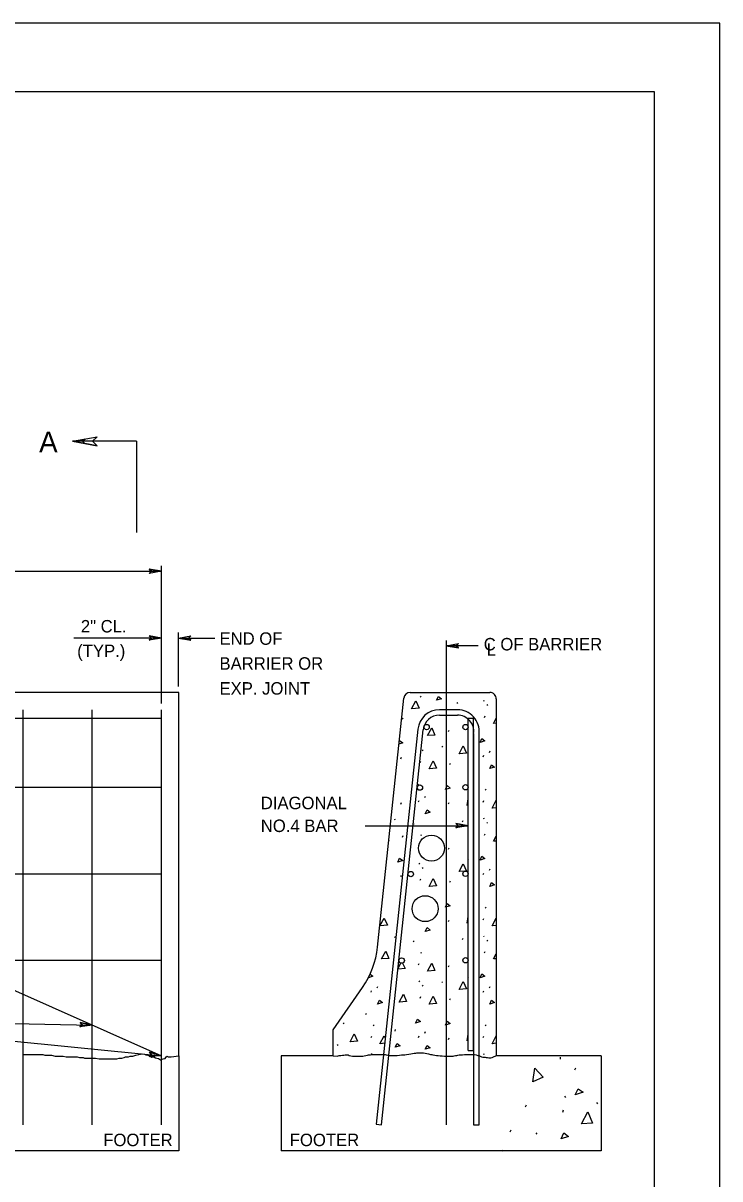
# Model space of a CAD drawing. Extents: x -113.6 to -105.1, y -201.8 to -190.8.
# Drawn here: x -108.47 to -105.11, y -196.35 to -190.78 of the extents above; entities that cross this region are included whole.
import ezdxf

# ---------------------------------------------------------------- set-up
doc = ezdxf.new("R2010")
doc.units = 0
for name, color, linetype in [('BORD-LINE', 7, 'Continuous'), ('CLIN', 7, 'Continuous'), ('DETL-PATT', 7, 'Continuous'), ('Level 10', 7, 'Continuous'), ('Level 12', 7, 'Continuous'), ('LGHT-UTIL_P', 7, 'Continuous'), ('SUBS-FOOT_P', 7, 'Continuous'), ('SUPR-PARA_P', 7, 'Continuous'), ('SUPR-RFRC', 7, 'Continuous'), ('USER-CLIP', 7, 'Continuous')]:
    doc.layers.add(name, color=color, linetype=linetype)

msp = doc.modelspace()

# ---------------------------------------------------------------- linework, layer by layer
at = {"layer": 'BORD-LINE'}
msp.add_lwpolyline([(-112.8058, -191.1077), (-105.4316, -191.1077), (-105.4316, -201.4608), (-112.8058, -201.4608)], close=True, dxfattribs=at)
at = {"layer": 'CLIN'}
msp.add_line((-106.4326, -193.7529), (-106.4326, -196.0862), dxfattribs=at)
at = {"layer": 'DETL-PATT'}
for p, q in [((-106.5997, -194.0811), (-106.5794, -194.0429)), ((-106.5794, -194.0429), (-106.5637, -194.078)), ((-106.5575, -194.0209), (-106.5545, -194.0253)), ((-106.3813, -194.0518), (-106.3783, -194.0564)), ((-106.2538, -194.0402), (-106.2508, -194.0448)), ((-106.2375, -194.0614), (-106.2345, -194.0661)), ((-106.6436, -194.1323), (-106.6407, -194.1255)), ((-106.5637, -194.078), (-106.5989, -194.0811)), ((-106.2476, -194.1227), (-106.2447, -194.1161)), ((-106.2047, -194.1524), (-106.1914, -194.1273)), ((-106.4219, -194.1909), (-106.4189, -194.1841)), ((-106.1914, -194.1513), (-106.2039, -194.1524)), ((-106.3286, -194.2386), (-106.3269, -194.2412)), ((-106.5484, -194.2791), (-106.5454, -194.2838)), ((-106.4537, -194.2618), (-106.4507, -194.2664)), ((-106.3708, -194.2988), (-106.3505, -194.2607)), ((-106.3348, -194.2958), (-106.37, -194.2988)), ((-106.3505, -194.2607), (-106.3348, -194.2958)), ((-106.2248, -194.2914), (-106.2218, -194.2846)), ((-106.6512, -194.3219), (-106.6482, -194.3153)), ((-106.5585, -194.3405), (-106.5556, -194.3338)), ((-106.4147, -194.3501), (-106.4117, -194.3433)), ((-106.2551, -194.3123), (-106.2522, -194.3056)), ((-106.5721, -194.4583), (-106.5722, -194.4584)), ((-106.5706, -194.4433), (-106.5632, -194.4488)), ((-106.5357, -194.5091), (-106.5327, -194.5024)), ((-106.3313, -194.5475), (-106.3269, -194.5154)), ((-106.2447, -194.4695), (-106.2417, -194.4741)), ((-106.6509, -194.5404), (-106.6479, -194.5337)), ((-106.566, -194.5301), (-106.5631, -194.5234)), ((-106.4223, -194.5396), (-106.4192, -194.5331)), ((-106.3269, -194.5454), (-106.3306, -194.5471)), ((-106.2548, -194.5308), (-106.2519, -194.5241)), ((-106.1914, -194.5588), (-106.2112, -194.5605)), ((-106.6826, -194.6114), (-106.6796, -194.616)), ((-106.3542, -194.6263), (-106.3513, -194.6195)), ((-106.2538, -194.6075), (-106.2508, -194.6121)), ((-106.2375, -194.6287), (-106.2345, -194.6333)), ((-106.5907, -194.6342), (-106.5887, -194.6372)), ((-106.5556, -194.6872), (-106.5526, -194.6918)), ((-106.2476, -194.69), (-106.2447, -194.6833)), ((-106.6436, -194.6996), (-106.6407, -194.6928)), ((-106.2047, -194.7197), (-106.1914, -194.6946)), ((-106.1914, -194.7186), (-106.2039, -194.7197)), ((-106.4219, -194.7582), (-106.4189, -194.7514)), ((-106.5647, -194.8253), (-106.5616, -194.8299)), ((-106.5484, -194.8464), (-106.5454, -194.8511)), ((-106.3708, -194.8661), (-106.3505, -194.828)), ((-106.3505, -194.828), (-106.3348, -194.8631)), ((-106.3286, -194.8059), (-106.3269, -194.8085)), ((-106.2248, -194.8587), (-106.2218, -194.8519)), ((-106.6512, -194.8892), (-106.6482, -194.8826)), ((-106.5585, -194.9078), (-106.5556, -194.9011)), ((-106.3423, -194.8637), (-106.37, -194.8661)), ((-106.3348, -194.8631), (-106.3397, -194.8635)), ((-106.2551, -194.8796), (-106.2522, -194.8729)), ((-106.4147, -194.9174), (-106.4117, -194.9106)), ((-106.2447, -195.0368), (-106.2417, -195.0414)), ((-106.4223, -195.1069), (-106.4192, -195.1004)), ((-106.3313, -195.1147), (-106.3269, -195.0827)), ((-106.3269, -195.1127), (-106.3306, -195.1144)), ((-106.2548, -195.0981), (-106.2519, -195.0914)), ((-106.1914, -195.1261), (-106.2112, -195.1278)), ((-106.6826, -195.1787), (-106.6796, -195.1832)), ((-106.3542, -195.1936), (-106.3513, -195.1868)), ((-106.2538, -195.1748), (-106.2508, -195.1794)), ((-106.5917, -195.2), (-106.5887, -195.2045)), ((-106.2375, -195.196), (-106.2345, -195.2006)), ((-106.5556, -195.2545), (-106.5526, -195.2591)), ((-106.2476, -195.2573), (-106.2447, -195.2506)), ((-106.2047, -195.287), (-106.1914, -195.2619)), ((-106.1914, -195.2859), (-106.2039, -195.287)), ((-106.6643, -195.3318), (-106.6512, -195.307)), ((-106.5657, -195.3159), (-106.5628, -195.3091)), ((-106.4219, -195.3255), (-106.4189, -195.3187)), ((-106.5647, -195.3926), (-106.5616, -195.3971)), ((-106.4537, -195.3964), (-106.4507, -195.401)), ((-106.3708, -195.4334), (-106.3505, -195.3953)), ((-106.3505, -195.3953), (-106.3348, -195.4304)), ((-106.3286, -195.3732), (-106.3269, -195.3758)), ((-106.7949, -195.4469), (-106.792, -195.4402)), ((-106.7646, -195.426), (-106.7616, -195.4192)), ((-106.5484, -195.4137), (-106.5454, -195.4184)), ((-106.3348, -195.4304), (-106.37, -195.4334)), ((-106.2551, -195.4469), (-106.2522, -195.4402)), ((-106.2248, -195.426), (-106.2218, -195.4192)), ((-106.5585, -195.4751), (-106.5556, -195.4684)), ((-106.4147, -195.4846), (-106.4117, -195.4779)), ((-106.8207, -195.5495), (-106.8176, -195.5541)), ((-106.9283, -195.5945), (-106.9254, -195.5991)), ((-106.7845, -195.6041), (-106.7815, -195.6087)), ((-106.6794, -195.6341), (-106.6764, -195.6274)), ((-106.2447, -195.6041), (-106.2417, -195.6087)), ((-106.7946, -195.6654), (-106.7917, -195.6587)), ((-106.566, -195.6646), (-106.5631, -195.658)), ((-106.5357, -195.6437), (-106.5327, -195.6369)), ((-106.4223, -195.6742), (-106.4192, -195.6677)), ((-106.3313, -195.682), (-106.3269, -195.65)), ((-106.3269, -195.68), (-106.3306, -195.6817)), ((-106.2548, -195.6654), (-106.2519, -195.6587)), ((-106.9575, -195.699), (-106.9546, -195.7035)), ((-106.7936, -195.7421), (-106.7906, -195.7467)), ((-106.7286, -195.6932), (-106.751, -195.6951)), ((-106.6781, -195.7126), (-106.669, -195.6938)), ((-106.6542, -195.7051), (-106.6781, -195.7126)), ((-106.669, -195.6938), (-106.6542, -195.7051)), ((-106.2538, -195.7421), (-106.2508, -195.7467)), ((-106.1914, -195.6934), (-106.2112, -195.6951)), ((-105.8847, -195.7593), (-105.8834, -195.7696)), ((-105.8126, -195.8212), (-105.8087, -195.8109)), ((-105.8628, -195.9487), (-105.859, -195.9551)), ((-106.0509, -196.0002), (-106.0457, -195.9899)), ((-105.8718, -196.0247), (-105.868, -196.0144)), ((-105.7095, -195.9783), (-105.7044, -195.9848)), ((-106.125, -196.1201), (-106.1198, -196.1098)), ((-106.0007, -196.1239), (-105.9955, -196.1316))]:
    msp.add_line(p, q, dxfattribs=at)
for points in [[(-106.4791, -194.0402), (-106.4701, -194.0216), (-106.4553, -194.0328), (-106.4791, -194.0402)], [(-106.5228, -194.211), (-106.5026, -194.1729), (-106.4868, -194.208), (-106.522, -194.211)], [(-106.6589, -194.2382), (-106.657, -194.2342), (-106.6419, -194.2454), (-106.6603, -194.2512)], [(-106.2699, -194.2433), (-106.261, -194.2246), (-106.246, -194.2357), (-106.2699, -194.2433)], [(-106.5156, -194.3702), (-106.4954, -194.332), (-106.4797, -194.3671), (-106.5148, -194.3702)], [(-106.2233, -194.3698), (-106.2143, -194.3511), (-106.1995, -194.3623), (-106.2233, -194.3698)], [(-106.4369, -194.4707), (-106.4281, -194.4519), (-106.413, -194.4632), (-106.4369, -194.4707)], [(-106.5341, -194.5876), (-106.5252, -194.5688), (-106.5104, -194.5801), (-106.5341, -194.5876)], [(-106.2119, -194.5605), (-106.1917, -194.5224), (-106.1914, -194.5231)], [(-106.7092, -194.7152), (-106.7086, -194.7167), (-106.7094, -194.7168)], [(-106.2699, -194.8106), (-106.261, -194.7919), (-106.246, -194.803), (-106.2699, -194.8106)], [(-106.6659, -194.8202), (-106.657, -194.8015), (-106.6419, -194.8127), (-106.6659, -194.8202)], [(-106.5156, -194.9375), (-106.4954, -194.8993), (-106.4797, -194.9344), (-106.5148, -194.9375)], [(-106.2233, -194.9371), (-106.2143, -194.9183), (-106.1995, -194.9296), (-106.2233, -194.9371)], [(-106.4369, -195.038), (-106.4281, -195.0192), (-106.413, -195.0305), (-106.4369, -195.038)], [(-106.7517, -195.1278), (-106.7315, -195.0897), (-106.7158, -195.1248), (-106.751, -195.1278)], [(-106.2119, -195.1278), (-106.1917, -195.0897), (-106.1914, -195.0904)], [(-106.5341, -195.1549), (-106.5252, -195.1361), (-106.5104, -195.1474), (-106.5341, -195.1549)], [(-106.7445, -195.287), (-106.7243, -195.2489), (-106.7086, -195.284), (-106.7437, -195.287)], [(-106.6425, -195.3067), (-106.6306, -195.333), (-106.6647, -195.3359)], [(-106.5228, -195.3456), (-106.5026, -195.3075), (-106.4868, -195.3426), (-106.522, -195.3456)], [(-106.7995, -195.3601), (-106.7858, -195.3703), (-106.8078, -195.3773)], [(-106.2699, -195.3779), (-106.261, -195.3592), (-106.246, -195.3703), (-106.2699, -195.3779)], [(-106.6593, -195.4952), (-106.6391, -195.4571), (-106.6234, -195.4921), (-106.6586, -195.4952)], [(-106.5156, -195.5047), (-106.4954, -195.4666), (-106.4797, -195.5017), (-106.5148, -195.5047)], [(-106.7631, -195.5044), (-106.7541, -195.4856), (-106.7393, -195.4969), (-106.7631, -195.5044)], [(-106.2233, -195.5044), (-106.2143, -195.4856), (-106.1995, -195.4969), (-106.2233, -195.5044)], [(-106.5808, -195.5957), (-106.5718, -195.5769), (-106.5568, -195.5881), (-106.5808, -195.5957)], [(-106.4369, -195.6053), (-106.4281, -195.5865), (-106.413, -195.5978), (-106.4369, -195.6053)], [(-106.8955, -195.6855), (-106.8754, -195.6475), (-106.8595, -195.6825), (-106.8947, -195.6855)], [(-106.7517, -195.6951), (-106.7315, -195.657), (-106.7261, -195.6691)], [(-106.2119, -195.6951), (-106.1917, -195.657), (-106.1914, -195.6577)], [(-106.5341, -195.7221), (-106.5252, -195.7034), (-106.5104, -195.7146), (-106.5341, -195.7221)], [(-106.0148, -195.8791), (-106.0058, -195.8134), (-105.9659, -195.8559), (-106.0148, -195.8791)], [(-105.8113, -195.941), (-105.7971, -195.9126), (-105.7739, -195.9294), (-105.8113, -195.941)], [(-105.7817, -196.0814), (-105.7507, -196.0234), (-105.7275, -196.0775), (-105.7817, -196.0814)], [(-105.8796, -196.1535), (-105.8667, -196.1252), (-105.8435, -196.1419), (-105.8796, -196.1535)], [(-106.1648, -196.2112), (-106.163, -196.2076), (-106.1583, -196.2112)]]:
    msp.add_lwpolyline(points, dxfattribs=at)
at = {"layer": 'Level 10'}
for p, q in [((-108.2326, -192.7927), (-108.1133, -192.7717)), ((-108.2326, -192.7927), (-108.173, -192.7822)), ((-108.2326, -192.7927), (-108.173, -192.8032)), ((-108.2326, -192.7927), (-108.1133, -192.8137)), ((-107.9246, -192.7927), (-108.2326, -192.7927)), ((-108.1843, -192.7927), (-108.173, -192.7822)), ((-108.173, -192.8032), (-108.1843, -192.7927)), ((-108.136, -192.7927), (-108.1133, -192.7717)), ((-108.1133, -192.8137), (-108.136, -192.7927)), ((-107.9246, -192.7927), (-107.9246, -193.2322)), ((-107.8038, -194.0567), (-107.8038, -193.3935)), ((-111.4705, -193.4185), (-107.8038, -193.4185)), ((-107.8038, -193.4185), (-107.8635, -193.408)), ((-107.8635, -193.408), (-107.8521, -193.4185)), ((-107.8038, -193.4185), (-107.8635, -193.429)), ((-107.8521, -193.4185), (-107.8635, -193.429)), ((-107.8038, -193.7407), (-107.8635, -193.7302)), ((-107.8635, -193.7302), (-107.8521, -193.7407)), ((-107.7223, -193.9734), (-107.7223, -193.7132)), ((-107.7223, -193.7407), (-107.6628, -193.7302)), ((-107.674, -193.7407), (-107.6628, -193.7302)), ((-107.8038, -193.7407), (-108.2267, -193.7407)), ((-107.8038, -193.7407), (-107.8635, -193.7512)), ((-107.8521, -193.7407), (-107.8635, -193.7512)), ((-107.7223, -193.7407), (-107.5471, -193.7407)), ((-107.7223, -193.7407), (-107.6628, -193.7512)), ((-107.6628, -193.7512), (-107.674, -193.7407)), ((-106.4326, -193.7779), (-106.3729, -193.7674)), ((-106.2789, -193.7779), (-106.4326, -193.7779)), ((-106.4326, -193.7779), (-106.3729, -193.7884)), ((-106.3842, -193.7779), (-106.3729, -193.7674)), ((-106.3729, -193.7884), (-106.3842, -193.7779)), ((-106.8232, -194.6453), (-106.3269, -194.6453)), ((-106.3269, -194.6453), (-106.3865, -194.6348)), ((-106.3865, -194.6348), (-106.3752, -194.6453)), ((-106.3269, -194.6453), (-106.3865, -194.6558)), ((-106.3752, -194.6453), (-106.3865, -194.6558)), ((-109.5686, -195.5773), (-108.1372, -195.6052)), ((-109.5686, -195.5773), (-107.8038, -195.7529)), ((-108.1854, -195.6042), (-108.1968, -195.6145)), ((-108.1372, -195.6052), (-108.1968, -195.6145)), ((-108.1372, -195.6052), (-108.1965, -195.5936)), ((-108.1965, -195.5936), (-108.1854, -195.6042)), ((-107.8038, -195.7529), (-107.862, -195.7366)), ((-107.862, -195.7366), (-107.8519, -195.7481)), ((-107.8519, -195.7481), (-107.8641, -195.7575)), ((-107.8038, -195.7529), (-107.8641, -195.7575))]:
    msp.add_line(p, q, dxfattribs=at)
for points in [[(-108.1133, -192.8137), (-108.2326, -192.7927), (-108.1133, -192.7717), (-108.136, -192.7927)], [(-108.173, -192.8032), (-108.2326, -192.7927), (-108.173, -192.7822), (-108.1843, -192.7927)], [(-107.8635, -193.408), (-107.8038, -193.4185), (-107.8635, -193.429), (-107.8521, -193.4185)], [(-107.8635, -193.7302), (-107.8038, -193.7407), (-107.8635, -193.7512), (-107.8521, -193.7407)], [(-107.6628, -193.7512), (-107.7223, -193.7407), (-107.6628, -193.7302), (-107.674, -193.7407)], [(-106.3729, -193.7884), (-106.4326, -193.7779), (-106.3729, -193.7674), (-106.3842, -193.7779)], [(-106.3865, -194.6348), (-106.3269, -194.6453), (-106.3865, -194.6558), (-106.3752, -194.6453)], [(-108.1965, -195.5936), (-108.1372, -195.6052), (-108.1968, -195.6145), (-108.1854, -195.6042)], [(-107.862, -195.7366), (-107.8038, -195.7529), (-107.8641, -195.7575), (-107.8519, -195.7481)]]:
    msp.add_lwpolyline(points, close=True, dxfattribs=at)
at = {"layer": 'LGHT-UTIL_P'}
for centre in [(-106.5037, -194.7529), (-106.5037, -194.7529), (-106.5345, -195.0446), (-106.5345, -195.0446)]:
    msp.add_circle(centre, 0.0625, dxfattribs=at)
at = {"layer": 'SUBS-FOOT_P'}
for p, q in [((-107.7205, -195.7529), (-107.7205, -196.2112)), ((-107.2279, -195.7529), (-107.2279, -196.2112)), ((-106.9779, -195.7529), (-107.2279, -195.7529)), ((-105.6862, -195.7529), (-106.1914, -195.7529)), ((-105.6862, -195.7529), (-105.6862, -196.2112)), ((-107.7205, -196.2112), (-112.302, -196.2112)), ((-105.6862, -196.2112), (-107.2279, -196.2112))]:
    msp.add_line(p, q, dxfattribs=at)
for points in [[(-108.4714, -195.7476), (-108.4608, -195.7476), (-108.4431, -195.7476), (-108.4255, -195.7476), (-108.4113, -195.7476), (-108.3972, -195.7476), (-108.3901, -195.7476), (-108.3831, -195.7476), (-108.376, -195.7476), (-108.3654, -195.7511), (-108.3513, -195.7511), (-108.3336, -195.7511), (-108.3159, -195.7546), (-108.3053, -195.7546), (-108.2983, -195.7546), (-108.2912, -195.7546), (-108.2841, -195.7546), (-108.2771, -195.7546), (-108.2629, -195.7582), (-108.2523, -195.7582), (-108.2453, -195.7582), (-108.2311, -195.7582), (-108.2241, -195.7582), (-108.2099, -195.7582), (-108.1993, -195.7617), (-108.1887, -195.7617), (-108.1817, -195.7617), (-108.1746, -195.7653), (-108.1675, -195.7653), (-108.1605, -195.7653), (-108.1499, -195.7653), (-108.1428, -195.7653), (-108.1287, -195.7653), (-108.1216, -195.7653), (-108.1039, -195.7688), (-108.0933, -195.7688), (-108.0827, -195.7688), (-108.0721, -195.7688), (-108.0615, -195.7688), (-108.0545, -195.7688), (-108.0474, -195.7688), (-108.0333, -195.7688), (-108.0262, -195.7688), (-108.0192, -195.7688), (-108.0086, -195.7653), (-108.0015, -195.7653), (-107.9944, -195.7653), (-107.9838, -195.7617), (-107.9768, -195.7582), (-107.9697, -195.7582), (-107.9626, -195.7582), (-107.9556, -195.7546), (-107.9414, -195.7546), (-107.9273, -195.7511), (-107.9132, -195.7476), (-107.8955, -195.744), (-107.8865, -195.7461), (-107.8787, -195.7486), (-107.8693, -195.75), (-107.8665, -195.7523), (-107.8595, -195.7536), (-107.8519, -195.7599), (-107.8406, -195.7578), (-107.8329, -195.7628), (-107.827, -195.7645), (-107.819, -195.7673), (-107.8083, -195.7724), (-107.7966, -195.7679), (-107.786, -195.7672), (-107.7789, -195.7546), (-107.7718, -195.7582), (-107.7648, -195.7582), (-107.7577, -195.7582), (-107.7205, -195.7529)], [(-106.9779, -195.7529), (-106.9584, -195.7548), (-106.948, -195.7527), (-106.9407, -195.7517), (-106.9324, -195.7506), (-106.9261, -195.7506), (-106.9199, -195.7496), (-106.9147, -195.7496), (-106.9053, -195.7496), (-106.9001, -195.7517), (-106.8918, -195.7537), (-106.8845, -195.7548), (-106.8752, -195.7558), (-106.8689, -195.7558), (-106.8627, -195.7558), (-106.8544, -195.7558), (-106.8481, -195.7548), (-106.8408, -195.7548), (-106.8336, -195.7548), (-106.8273, -195.7537), (-106.82, -195.7517), (-106.8117, -195.7506), (-106.8065, -195.7496), (-106.7971, -195.7485), (-106.7878, -195.7475), (-106.7774, -195.7475), (-106.768, -195.7475), (-106.7545, -195.7465), (-106.7472, -195.7465), (-106.741, -195.7465), (-106.7316, -195.7465), (-106.7264, -195.7475), (-106.7212, -195.7485), (-106.7139, -195.7506), (-106.7046, -195.7517), (-106.6973, -195.7517), (-106.6879, -195.7517), (-106.6786, -195.7517), (-106.6692, -195.7517), (-106.6578, -195.7506), (-106.6473, -195.7496), (-106.6401, -195.7496), (-106.6317, -195.7485), (-106.6234, -195.7465), (-106.613, -195.7454), (-106.6026, -195.7444), (-106.587, -195.7412), (-106.5797, -195.7402), (-106.5735, -195.7392), (-106.5641, -195.7392), (-106.5537, -195.7392), (-106.5485, -195.7392), (-106.5423, -195.7392), (-106.534, -195.7402), (-106.5267, -195.7423), (-106.5184, -195.7433), (-106.508, -195.7465), (-106.5028, -195.7475), (-106.4965, -195.7496), (-106.4871, -195.7506), (-106.4799, -195.7517), (-106.4715, -195.7527), (-106.4622, -195.7537), (-106.4518, -195.7537), (-106.4403, -195.7548), (-106.4289, -195.7548), (-106.4206, -195.7548), (-106.407, -195.7548), (-106.3998, -195.7548), (-106.3946, -195.7537), (-106.3883, -195.7517), (-106.3821, -195.7517), (-106.3769, -195.7506), (-106.3696, -195.7496), (-106.3623, -195.7485), (-106.355, -195.7485), (-106.3446, -195.7475), (-106.3353, -195.7465), (-106.3259, -195.7465), (-106.3145, -195.7465), (-106.3082, -195.7465), (-106.303, -195.7465), (-106.2968, -195.7465), (-106.2885, -195.7496), (-106.2812, -195.7527), (-106.2727, -195.7543), (-106.2631, -195.758), (-106.2571, -195.7598), (-106.2492, -195.7601), (-106.2449, -195.7609), (-106.2397, -195.7619), (-106.2333, -195.7623), (-106.2278, -195.7635), (-106.2216, -195.7635), (-106.2181, -195.7626), (-106.2119, -195.7615), (-106.2043, -195.7588), (-106.1939, -195.7534), (-106.1905, -195.7527)]]:
    msp.add_lwpolyline(points, dxfattribs=at)
at = {"layer": 'SUPR-PARA_P'}
for p, q in [((-107.7205, -194.0029), (-112.302, -194.0029)), ((-107.7205, -195.7529), (-107.7205, -194.0029)), ((-106.1914, -194.0341), (-106.1914, -195.7529)), ((-106.9779, -195.7529), (-106.9779, -195.6279))]:
    msp.add_line(p, q, dxfattribs=at)
for points in [[(-106.606, -194.0029), (-106.2228, -194.0029)], [(-106.7635, -195.2297), (-106.6371, -194.0308)], [(-106.9779, -195.6279), (-106.836, -195.4241)]]:
    msp.add_lwpolyline(points, dxfattribs=at)
for centre, radius, start, end in [((-106.606, -194.0341), 0.0313, 90, 173.9793), ((-106.2227, -194.0341), 0.0313, 0, 90.3105), ((-107.1779, -195.186), 0.4167, 325.1455, 353.9793)]:
    msp.add_arc(centre, radius, start, end, dxfattribs=at)
at = {"layer": 'SUPR-RFRC'}
for p, q in [((-107.8038, -194.1279), (-112.302, -194.1279)), ((-111.4705, -194.1279), (-107.8038, -195.7529)), ((-108.4705, -196.0862), (-108.4705, -194.0862)), ((-108.1372, -196.0862), (-108.1372, -194.0862)), ((-107.8038, -196.0862), (-107.8038, -194.0862)), ((-106.3783, -194.0862), (-106.4653, -194.0862)), ((-106.4653, -194.1123), (-106.3783, -194.1123)), ((-106.3269, -195.7284), (-106.3269, -194.1261)), ((-106.3269, -194.1261), (-106.3008, -194.1261)), ((-106.3008, -195.7288), (-106.3008, -194.1261)), ((-106.5689, -194.1795), (-106.7698, -196.0835)), ((-106.7439, -196.0862), (-106.543, -194.1822)), ((-106.3008, -194.2002), (-106.3008, -196.0862)), ((-106.2747, -196.0862), (-106.2747, -194.2013)), ((-107.8038, -194.4612), (-112.302, -194.4612)), ((-107.8038, -194.8779), (-112.302, -194.8779)), ((-107.8038, -195.2946), (-112.302, -195.2946)), ((-106.3269, -195.7284), (-106.3008, -195.7284)), ((-106.7698, -196.0835), (-106.7439, -196.0862)), ((-106.3008, -196.0862), (-106.2747, -196.0862))]:
    msp.add_line(p, q, dxfattribs=at)
for centre in [(-106.5271, -194.1695), (-106.3399, -194.1695), (-106.5594, -194.4612), (-106.3399, -194.4598), (-106.6033, -194.8779), (-106.3399, -194.8765), (-106.6473, -195.2946), (-106.3399, -195.2932)]:
    msp.add_circle(centre, 0.013, dxfattribs=at)
for centre, radius, start, end in [((-106.4653, -194.1904), 0.1042, 90, 173.9793), ((-106.4653, -194.1904), 0.0781, 90, 173.9793), ((-106.3783, -194.1904), 0.1042, 353.9793, 90), ((-106.3783, -194.1904), 0.0781, 352.8084, 90)]:
    msp.add_arc(centre, radius, start, end, dxfattribs=at)
at = {"layer": 'USER-CLIP'}
msp.add_lwpolyline([(-105.1147, -190.7777), (-113.6147, -190.7777), (-113.6147, -201.7777), (-105.1147, -201.7777)], close=True, dxfattribs=at)

# ---------------------------------------------------------------- texts
at = {"layer": 'Level 12'}
for s, height, p in [('A', 0.1, (-108.3935, -192.8457)), ('END OF', 0.06, (-107.5247, -193.7732)), ('C OF BARRIER', 0.060001, (-106.2521, -193.8002)), ('(TYP.)', 0.06, (-108.2101, -193.8324)), ('L', 0.06, (-106.238, -193.8256)), ('BARRIER OR', 0.06, (-107.5247, -193.8932)), ('EXP. JOINT', 0.06, (-107.5247, -194.0132)), ('DIAGONAL', 0.06, (-107.3258, -194.5653)), ('NO.4 BAR', 0.06, (-107.3258, -194.6753)), ('FOOTER', 0.06, (-108.0845, -196.1888)), ('FOOTER', 0.06, (-107.1862, -196.1888))]:
    msp.add_text(s, height=height, dxfattribs=at).set_placement(p)
msp.add_text('2" CL.', height=0.06, rotation=360, dxfattribs=at).set_placement((-108.1925, -193.7137))

doc.saveas('drawing.dxf')
